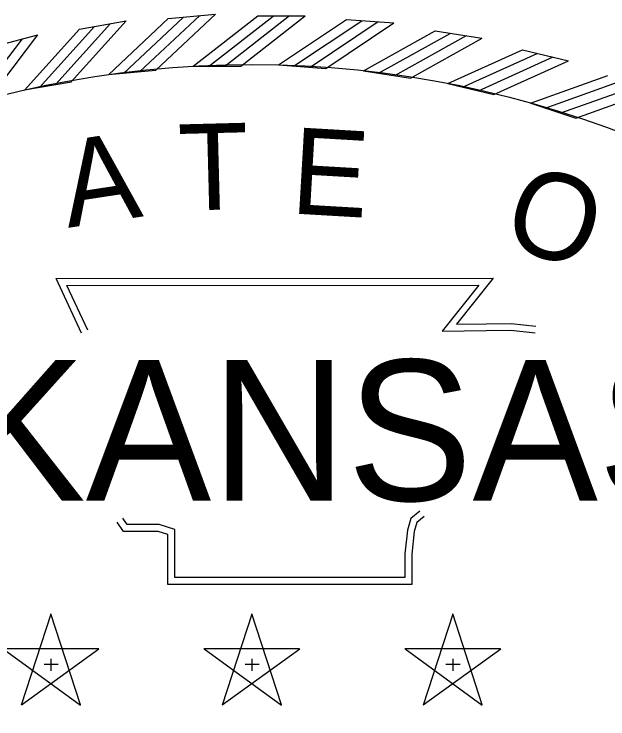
# Model space of a CAD drawing. Extents: x 18 to 1228740, y 11 to 152440.
# Drawn here: x 17.7475 to 17.7948, y 10.9361 to 10.9922 of the extents above; entities that cross this region are included whole.
import ezdxf

# ---------------------------------------------------------------- set-up
doc = ezdxf.new("R2010")
doc.units = 0
for name, color, linetype in [('B_StampERBB', 7, 'Continuous'), ('B_StampHSS', 7, 'Continuous'), ('B_StampJSB', 7, 'Continuous'), ('B_StampSCR', 7, 'Continuous'), ('B_StampSFH', 7, 'Continuous')]:
    doc.layers.add(name, color=color, linetype=linetype)

msp = doc.modelspace()

# ---------------------------------------------------------------- linework, layer by layer
at = {"layer": 'B_StampERBB'}
for p, q in [((17.759782, 10.99184), (17.763536, 10.992186)), ((17.766921, 10.99205), (17.770691, 10.99205)), ((17.752726, 10.990997), (17.756438, 10.991651)), ((17.773983, 10.991767), (17.777742, 10.991491)), ((17.745763, 10.989574), (17.749409, 10.990533)), ((17.78103, 10.990852), (17.784754, 10.990266)), ((17.787978, 10.989358), (17.791641, 10.988467)), ((17.768557, 10.988144), (17.772326, 10.987867)), ((17.755027, 10.987373), (17.75879, 10.98772)), ((17.761776, 10.988038), (17.765555, 10.988038)), ((17.775324, 10.987689), (17.779057, 10.987102)), ((17.748356, 10.986153), (17.752077, 10.986809)), ((17.78203, 10.986678), (17.785702, 10.985784)), ((17.78863, 10.985115), (17.792215, 10.983921)), ((17.750447, 10.944483), (17.748088, 10.937247)), ((17.752797, 10.937251), (17.750452, 10.944492)), ((17.766438, 10.944483), (17.764079, 10.937247)), ((17.768788, 10.937251), (17.766443, 10.944492)), ((17.782429, 10.944483), (17.78007, 10.937247)), ((17.784779, 10.937251), (17.782434, 10.944492)), ((17.754249, 10.941721), (17.746638, 10.941728)), ((17.746645, 10.941721), (17.752798, 10.937242)), ((17.748097, 10.937251), (17.754258, 10.941719)), ((17.77024, 10.941721), (17.762629, 10.941728)), ((17.762636, 10.941721), (17.768789, 10.937242)), ((17.764088, 10.937251), (17.770249, 10.941719)), ((17.786231, 10.941721), (17.77862, 10.941728)), ((17.778627, 10.941721), (17.78478, 10.937242)), ((17.780079, 10.937251), (17.786241, 10.941719)), ((17.749905, 10.940505), (17.751036, 10.940505)), ((17.750454, 10.940912), (17.750454, 10.939957)), ((17.765896, 10.940505), (17.767027, 10.940505)), ((17.766445, 10.940912), (17.766445, 10.939957)), ((17.781887, 10.940505), (17.783018, 10.940505)), ((17.782436, 10.940912), (17.782436, 10.939957))]:
    msp.add_line(p, q, dxfattribs=at)
for points in [[(17.757534, 10.987618), (17.762288, 10.992085)], [(17.758785, 10.987722), (17.763539, 10.992189)], [(17.761772, 10.988035), (17.766915, 10.992046)], [(17.764295, 10.988053), (17.769438, 10.992064)], [(17.765551, 10.988041), (17.770694, 10.992053)], [(17.752072, 10.986811), (17.756441, 10.991655)], [(17.755023, 10.987369), (17.759777, 10.991836)], [(17.756232, 10.987469), (17.760986, 10.991936)], [(17.762985, 10.988024), (17.768129, 10.992035)], [(17.768553, 10.988141), (17.773977, 10.991764)], [(17.769762, 10.988041), (17.775186, 10.991664)], [(17.77107, 10.987973), (17.776494, 10.991597)], [(17.772322, 10.98787), (17.777746, 10.991493)], [(17.748352, 10.986148), (17.752721, 10.990992)], [(17.749549, 10.986348), (17.753918, 10.991192)], [(17.750833, 10.986604), (17.755202, 10.991448)], [(17.745458, 10.985348), (17.749412, 10.990536)], [(17.775319, 10.987687), (17.781024, 10.99085)], [(17.776516, 10.987487), (17.782221, 10.99065)], [(17.777814, 10.987312), (17.783519, 10.990475)], [(17.74424, 10.98504), (17.748194, 10.990228)], [(17.779053, 10.987105), (17.784758, 10.990268)], [(17.782025, 10.986675), (17.787972, 10.989356)], [(17.783201, 10.986377), (17.789148, 10.989058)], [(17.78448, 10.986096), (17.790427, 10.988777)], [(17.785698, 10.985787), (17.791645, 10.988468)], [(17.788624, 10.985113), (17.794772, 10.987294)], [(17.789772, 10.984719), (17.79592, 10.9869)], [(17.791024, 10.984333), (17.797171, 10.986514)], [(17.792211, 10.983925), (17.798359, 10.986106)], [(17.752875, 10.966818), (17.750865, 10.97117), (17.785635, 10.97119), (17.78273, 10.96754), (17.785092, 10.967571), (17.787065, 10.967597), (17.789037, 10.967382)], [(17.753375, 10.967049), (17.751726, 10.97062), (17.784493, 10.970639), (17.781576, 10.966974), (17.785099, 10.96702), (17.787039, 10.967045), (17.788977, 10.966834)], [(17.780156, 10.952247), (17.779563, 10.951765), (17.779366, 10.951044), (17.77917, 10.949241), (17.77917, 10.946838), (17.75976, 10.946838), (17.75976, 10.950082), (17.75976, 10.950803), (17.758973, 10.951044), (17.756212, 10.951044), (17.755721, 10.951792)], [(17.779808, 10.952675), (17.779078, 10.95208), (17.778824, 10.951147), (17.778619, 10.949271), (17.778619, 10.947388), (17.760311, 10.947388), (17.760311, 10.950082), (17.760311, 10.951211), (17.759055, 10.951594), (17.756509, 10.951594), (17.756182, 10.952094)]]:
    msp.add_lwpolyline(points, dxfattribs=at)
at = {"layer": 'B_StampHSS'}
for p, q in [((17.759782, 10.99184), (17.763536, 10.992186)), ((17.766921, 10.99205), (17.770691, 10.99205)), ((17.752726, 10.990997), (17.756438, 10.991651)), ((17.773983, 10.991767), (17.777742, 10.991491)), ((17.745763, 10.989574), (17.749409, 10.990533)), ((17.78103, 10.990852), (17.784754, 10.990266)), ((17.787978, 10.989358), (17.791641, 10.988467)), ((17.768557, 10.988144), (17.772326, 10.987867)), ((17.755027, 10.987373), (17.75879, 10.98772)), ((17.761776, 10.988038), (17.765555, 10.988038)), ((17.775324, 10.987689), (17.779057, 10.987102)), ((17.748356, 10.986153), (17.752077, 10.986809)), ((17.78203, 10.986678), (17.785702, 10.985784)), ((17.78863, 10.985115), (17.792215, 10.983921)), ((17.750447, 10.944483), (17.748088, 10.937247)), ((17.752797, 10.937251), (17.750452, 10.944492)), ((17.766438, 10.944483), (17.764079, 10.937247)), ((17.768788, 10.937251), (17.766443, 10.944492)), ((17.782429, 10.944483), (17.78007, 10.937247)), ((17.784779, 10.937251), (17.782434, 10.944492)), ((17.754249, 10.941721), (17.746638, 10.941728)), ((17.746645, 10.941721), (17.752798, 10.937242)), ((17.748097, 10.937251), (17.754258, 10.941719)), ((17.77024, 10.941721), (17.762629, 10.941728)), ((17.762636, 10.941721), (17.768789, 10.937242)), ((17.764088, 10.937251), (17.770249, 10.941719)), ((17.786231, 10.941721), (17.77862, 10.941728)), ((17.778627, 10.941721), (17.78478, 10.937242)), ((17.780079, 10.937251), (17.786241, 10.941719)), ((17.749905, 10.940505), (17.751036, 10.940505)), ((17.750454, 10.940912), (17.750454, 10.939957)), ((17.765896, 10.940505), (17.767027, 10.940505)), ((17.766445, 10.940912), (17.766445, 10.939957)), ((17.781887, 10.940505), (17.783018, 10.940505)), ((17.782436, 10.940912), (17.782436, 10.939957))]:
    msp.add_line(p, q, dxfattribs=at)
for points in [[(17.757534, 10.987618), (17.762288, 10.992085)], [(17.758785, 10.987722), (17.763539, 10.992189)], [(17.761772, 10.988035), (17.766915, 10.992046)], [(17.764295, 10.988053), (17.769438, 10.992064)], [(17.765551, 10.988041), (17.770694, 10.992053)], [(17.752072, 10.986811), (17.756441, 10.991655)], [(17.755023, 10.987369), (17.759777, 10.991836)], [(17.756232, 10.987469), (17.760986, 10.991936)], [(17.762985, 10.988024), (17.768129, 10.992035)], [(17.768553, 10.988141), (17.773977, 10.991764)], [(17.769762, 10.988041), (17.775186, 10.991664)], [(17.77107, 10.987973), (17.776494, 10.991597)], [(17.772322, 10.98787), (17.777746, 10.991493)], [(17.748352, 10.986148), (17.752721, 10.990992)], [(17.749549, 10.986348), (17.753918, 10.991192)], [(17.750833, 10.986604), (17.755202, 10.991448)], [(17.745458, 10.985348), (17.749412, 10.990536)], [(17.775319, 10.987687), (17.781024, 10.99085)], [(17.776516, 10.987487), (17.782221, 10.99065)], [(17.777814, 10.987312), (17.783519, 10.990475)], [(17.74424, 10.98504), (17.748194, 10.990228)], [(17.779053, 10.987105), (17.784758, 10.990268)], [(17.782025, 10.986675), (17.787972, 10.989356)], [(17.783201, 10.986377), (17.789148, 10.989058)], [(17.78448, 10.986096), (17.790427, 10.988777)], [(17.785698, 10.985787), (17.791645, 10.988468)], [(17.788624, 10.985113), (17.794772, 10.987294)], [(17.789772, 10.984719), (17.79592, 10.9869)], [(17.791024, 10.984333), (17.797171, 10.986514)], [(17.792211, 10.983925), (17.798359, 10.986106)], [(17.752875, 10.966818), (17.750865, 10.97117), (17.785635, 10.97119), (17.78273, 10.96754), (17.785092, 10.967571), (17.787065, 10.967597), (17.789037, 10.967382)], [(17.753375, 10.967049), (17.751726, 10.97062), (17.784493, 10.970639), (17.781576, 10.966974), (17.785099, 10.96702), (17.787039, 10.967045), (17.788977, 10.966834)], [(17.780156, 10.952247), (17.779563, 10.951765), (17.779366, 10.951044), (17.77917, 10.949241), (17.77917, 10.946838), (17.75976, 10.946838), (17.75976, 10.950082), (17.75976, 10.950803), (17.758973, 10.951044), (17.756212, 10.951044), (17.755721, 10.951792)], [(17.779808, 10.952675), (17.779078, 10.95208), (17.778824, 10.951147), (17.778619, 10.949271), (17.778619, 10.947388), (17.760311, 10.947388), (17.760311, 10.950082), (17.760311, 10.951211), (17.759055, 10.951594), (17.756509, 10.951594), (17.756182, 10.952094)]]:
    msp.add_lwpolyline(points, dxfattribs=at)
at = {"layer": 'B_StampJSB'}
for p, q in [((17.759782, 10.99184), (17.763536, 10.992186)), ((17.766921, 10.99205), (17.770691, 10.99205)), ((17.752726, 10.990997), (17.756438, 10.991651)), ((17.773983, 10.991767), (17.777742, 10.991491)), ((17.745763, 10.989574), (17.749409, 10.990533)), ((17.78103, 10.990852), (17.784754, 10.990266)), ((17.787978, 10.989358), (17.791641, 10.988467)), ((17.768557, 10.988144), (17.772326, 10.987867)), ((17.755027, 10.987373), (17.75879, 10.98772)), ((17.761776, 10.988038), (17.765555, 10.988038)), ((17.775324, 10.987689), (17.779057, 10.987102)), ((17.748356, 10.986153), (17.752077, 10.986809)), ((17.78203, 10.986678), (17.785702, 10.985784)), ((17.78863, 10.985115), (17.792215, 10.983921)), ((17.750447, 10.944483), (17.748088, 10.937247)), ((17.752797, 10.937251), (17.750452, 10.944492)), ((17.766438, 10.944483), (17.764079, 10.937247)), ((17.768788, 10.937251), (17.766443, 10.944492)), ((17.782429, 10.944483), (17.78007, 10.937247)), ((17.784779, 10.937251), (17.782434, 10.944492)), ((17.754249, 10.941721), (17.746638, 10.941728)), ((17.746645, 10.941721), (17.752798, 10.937242)), ((17.748097, 10.937251), (17.754258, 10.941719)), ((17.77024, 10.941721), (17.762629, 10.941728)), ((17.762636, 10.941721), (17.768789, 10.937242)), ((17.764088, 10.937251), (17.770249, 10.941719)), ((17.786231, 10.941721), (17.77862, 10.941728)), ((17.778627, 10.941721), (17.78478, 10.937242)), ((17.780079, 10.937251), (17.786241, 10.941719)), ((17.749905, 10.940505), (17.751036, 10.940505)), ((17.750454, 10.940912), (17.750454, 10.939957)), ((17.765896, 10.940505), (17.767027, 10.940505)), ((17.766445, 10.940912), (17.766445, 10.939957)), ((17.781887, 10.940505), (17.783018, 10.940505)), ((17.782436, 10.940912), (17.782436, 10.939957))]:
    msp.add_line(p, q, dxfattribs=at)
for points in [[(17.757534, 10.987618), (17.762288, 10.992085)], [(17.758785, 10.987722), (17.763539, 10.992189)], [(17.761772, 10.988035), (17.766915, 10.992046)], [(17.764295, 10.988053), (17.769438, 10.992064)], [(17.765551, 10.988041), (17.770694, 10.992053)], [(17.752072, 10.986811), (17.756441, 10.991655)], [(17.755023, 10.987369), (17.759777, 10.991836)], [(17.756232, 10.987469), (17.760986, 10.991936)], [(17.762985, 10.988024), (17.768129, 10.992035)], [(17.768553, 10.988141), (17.773977, 10.991764)], [(17.769762, 10.988041), (17.775186, 10.991664)], [(17.77107, 10.987973), (17.776494, 10.991597)], [(17.772322, 10.98787), (17.777746, 10.991493)], [(17.748352, 10.986148), (17.752721, 10.990992)], [(17.749549, 10.986348), (17.753918, 10.991192)], [(17.750833, 10.986604), (17.755202, 10.991448)], [(17.745458, 10.985348), (17.749412, 10.990536)], [(17.775319, 10.987687), (17.781024, 10.99085)], [(17.776516, 10.987487), (17.782221, 10.99065)], [(17.777814, 10.987312), (17.783519, 10.990475)], [(17.74424, 10.98504), (17.748194, 10.990228)], [(17.779053, 10.987105), (17.784758, 10.990268)], [(17.782025, 10.986675), (17.787972, 10.989356)], [(17.783201, 10.986377), (17.789148, 10.989058)], [(17.78448, 10.986096), (17.790427, 10.988777)], [(17.785698, 10.985787), (17.791645, 10.988468)], [(17.788624, 10.985113), (17.794772, 10.987294)], [(17.789772, 10.984719), (17.79592, 10.9869)], [(17.791024, 10.984333), (17.797171, 10.986514)], [(17.792211, 10.983925), (17.798359, 10.986106)], [(17.752875, 10.966818), (17.750865, 10.97117), (17.785635, 10.97119), (17.78273, 10.96754), (17.785092, 10.967571), (17.787065, 10.967597), (17.789037, 10.967382)], [(17.753375, 10.967049), (17.751726, 10.97062), (17.784493, 10.970639), (17.781576, 10.966974), (17.785099, 10.96702), (17.787039, 10.967045), (17.788977, 10.966834)], [(17.780156, 10.952247), (17.779563, 10.951765), (17.779366, 10.951044), (17.77917, 10.949241), (17.77917, 10.946838), (17.75976, 10.946838), (17.75976, 10.950082), (17.75976, 10.950803), (17.758973, 10.951044), (17.756212, 10.951044), (17.755721, 10.951792)], [(17.779808, 10.952675), (17.779078, 10.95208), (17.778824, 10.951147), (17.778619, 10.949271), (17.778619, 10.947388), (17.760311, 10.947388), (17.760311, 10.950082), (17.760311, 10.951211), (17.759055, 10.951594), (17.756509, 10.951594), (17.756182, 10.952094)]]:
    msp.add_lwpolyline(points, dxfattribs=at)
msp.add_circle((17.766447, 10.906117), 0.082054, dxfattribs=at)
at = {"layer": 'B_StampSCR'}
for p, q in [((17.759782, 10.99184), (17.763536, 10.992186)), ((17.766921, 10.99205), (17.770691, 10.99205)), ((17.752726, 10.990997), (17.756438, 10.991651)), ((17.773983, 10.991767), (17.777742, 10.991491)), ((17.745763, 10.989574), (17.749409, 10.990533)), ((17.78103, 10.990852), (17.784754, 10.990266)), ((17.787978, 10.989358), (17.791641, 10.988467)), ((17.768557, 10.988144), (17.772326, 10.987867)), ((17.755027, 10.987373), (17.75879, 10.98772)), ((17.761776, 10.988038), (17.765555, 10.988038)), ((17.775324, 10.987689), (17.779057, 10.987102)), ((17.748356, 10.986153), (17.752077, 10.986809)), ((17.78203, 10.986678), (17.785702, 10.985784)), ((17.78863, 10.985115), (17.792215, 10.983921)), ((17.750447, 10.944483), (17.748088, 10.937247)), ((17.752797, 10.937251), (17.750452, 10.944492)), ((17.766438, 10.944483), (17.764079, 10.937247)), ((17.768788, 10.937251), (17.766443, 10.944492)), ((17.782429, 10.944483), (17.78007, 10.937247)), ((17.784779, 10.937251), (17.782434, 10.944492)), ((17.754249, 10.941721), (17.746638, 10.941728)), ((17.746645, 10.941721), (17.752798, 10.937242)), ((17.748097, 10.937251), (17.754258, 10.941719)), ((17.77024, 10.941721), (17.762629, 10.941728)), ((17.762636, 10.941721), (17.768789, 10.937242)), ((17.764088, 10.937251), (17.770249, 10.941719)), ((17.786231, 10.941721), (17.77862, 10.941728)), ((17.778627, 10.941721), (17.78478, 10.937242)), ((17.780079, 10.937251), (17.786241, 10.941719)), ((17.749905, 10.940505), (17.751036, 10.940505)), ((17.750454, 10.940912), (17.750454, 10.939957)), ((17.765896, 10.940505), (17.767027, 10.940505)), ((17.766445, 10.940912), (17.766445, 10.939957)), ((17.781887, 10.940505), (17.783018, 10.940505)), ((17.782436, 10.940912), (17.782436, 10.939957))]:
    msp.add_line(p, q, dxfattribs=at)
for points in [[(17.757534, 10.987618), (17.762288, 10.992085)], [(17.758785, 10.987722), (17.763539, 10.992189)], [(17.761772, 10.988035), (17.766915, 10.992046)], [(17.764295, 10.988053), (17.769438, 10.992064)], [(17.765551, 10.988041), (17.770694, 10.992053)], [(17.752072, 10.986811), (17.756441, 10.991655)], [(17.755023, 10.987369), (17.759777, 10.991836)], [(17.756232, 10.987469), (17.760986, 10.991936)], [(17.762985, 10.988024), (17.768129, 10.992035)], [(17.768553, 10.988141), (17.773977, 10.991764)], [(17.769762, 10.988041), (17.775186, 10.991664)], [(17.77107, 10.987973), (17.776494, 10.991597)], [(17.772322, 10.98787), (17.777746, 10.991493)], [(17.748352, 10.986148), (17.752721, 10.990992)], [(17.749549, 10.986348), (17.753918, 10.991192)], [(17.750833, 10.986604), (17.755202, 10.991448)], [(17.745458, 10.985348), (17.749412, 10.990536)], [(17.775319, 10.987687), (17.781024, 10.99085)], [(17.776516, 10.987487), (17.782221, 10.99065)], [(17.777814, 10.987312), (17.783519, 10.990475)], [(17.74424, 10.98504), (17.748194, 10.990228)], [(17.779053, 10.987105), (17.784758, 10.990268)], [(17.782025, 10.986675), (17.787972, 10.989356)], [(17.783201, 10.986377), (17.789148, 10.989058)], [(17.78448, 10.986096), (17.790427, 10.988777)], [(17.785698, 10.985787), (17.791645, 10.988468)], [(17.788624, 10.985113), (17.794772, 10.987294)], [(17.789772, 10.984719), (17.79592, 10.9869)], [(17.791024, 10.984333), (17.797171, 10.986514)], [(17.792211, 10.983925), (17.798359, 10.986106)], [(17.752875, 10.966818), (17.750865, 10.97117), (17.785635, 10.97119), (17.78273, 10.96754), (17.785092, 10.967571), (17.787065, 10.967597), (17.789037, 10.967382)], [(17.753375, 10.967049), (17.751726, 10.97062), (17.784493, 10.970639), (17.781576, 10.966974), (17.785099, 10.96702), (17.787039, 10.967045), (17.788977, 10.966834)], [(17.780156, 10.952247), (17.779563, 10.951765), (17.779366, 10.951044), (17.77917, 10.949241), (17.77917, 10.946838), (17.75976, 10.946838), (17.75976, 10.950082), (17.75976, 10.950803), (17.758973, 10.951044), (17.756212, 10.951044), (17.755721, 10.951792)], [(17.779808, 10.952675), (17.779078, 10.95208), (17.778824, 10.951147), (17.778619, 10.949271), (17.778619, 10.947388), (17.760311, 10.947388), (17.760311, 10.950082), (17.760311, 10.951211), (17.759055, 10.951594), (17.756509, 10.951594), (17.756182, 10.952094)]]:
    msp.add_lwpolyline(points, dxfattribs=at)
at = {"layer": 'B_StampSFH'}
for p, q in [((17.759782, 10.99184), (17.763536, 10.992186)), ((17.766921, 10.99205), (17.770691, 10.99205)), ((17.752726, 10.990997), (17.756438, 10.991651)), ((17.773983, 10.991767), (17.777742, 10.991491)), ((17.745763, 10.989574), (17.749409, 10.990533)), ((17.78103, 10.990852), (17.784754, 10.990266)), ((17.787978, 10.989358), (17.791641, 10.988467)), ((17.768557, 10.988144), (17.772326, 10.987867)), ((17.755027, 10.987373), (17.75879, 10.98772)), ((17.761776, 10.988038), (17.765555, 10.988038)), ((17.775324, 10.987689), (17.779057, 10.987102)), ((17.748356, 10.986153), (17.752077, 10.986809)), ((17.78203, 10.986678), (17.785702, 10.985784)), ((17.78863, 10.985115), (17.792215, 10.983921)), ((17.750447, 10.944483), (17.748088, 10.937247)), ((17.752797, 10.937251), (17.750452, 10.944492)), ((17.766438, 10.944483), (17.764079, 10.937247)), ((17.768788, 10.937251), (17.766443, 10.944492)), ((17.782429, 10.944483), (17.78007, 10.937247)), ((17.784779, 10.937251), (17.782434, 10.944492)), ((17.754249, 10.941721), (17.746638, 10.941728)), ((17.746645, 10.941721), (17.752798, 10.937242)), ((17.748097, 10.937251), (17.754258, 10.941719)), ((17.77024, 10.941721), (17.762629, 10.941728)), ((17.762636, 10.941721), (17.768789, 10.937242)), ((17.764088, 10.937251), (17.770249, 10.941719)), ((17.786231, 10.941721), (17.77862, 10.941728)), ((17.778627, 10.941721), (17.78478, 10.937242)), ((17.780079, 10.937251), (17.786241, 10.941719)), ((17.749905, 10.940505), (17.751036, 10.940505)), ((17.750454, 10.940912), (17.750454, 10.939957)), ((17.765896, 10.940505), (17.767027, 10.940505)), ((17.766445, 10.940912), (17.766445, 10.939957)), ((17.781887, 10.940505), (17.783018, 10.940505)), ((17.782436, 10.940912), (17.782436, 10.939957))]:
    msp.add_line(p, q, dxfattribs=at)
for points in [[(17.757534, 10.987618), (17.762288, 10.992085)], [(17.758785, 10.987722), (17.763539, 10.992189)], [(17.761772, 10.988035), (17.766915, 10.992046)], [(17.764295, 10.988053), (17.769438, 10.992064)], [(17.765551, 10.988041), (17.770694, 10.992053)], [(17.752072, 10.986811), (17.756441, 10.991655)], [(17.755023, 10.987369), (17.759777, 10.991836)], [(17.756232, 10.987469), (17.760986, 10.991936)], [(17.762985, 10.988024), (17.768129, 10.992035)], [(17.768553, 10.988141), (17.773977, 10.991764)], [(17.769762, 10.988041), (17.775186, 10.991664)], [(17.77107, 10.987973), (17.776494, 10.991597)], [(17.772322, 10.98787), (17.777746, 10.991493)], [(17.748352, 10.986148), (17.752721, 10.990992)], [(17.749549, 10.986348), (17.753918, 10.991192)], [(17.750833, 10.986604), (17.755202, 10.991448)], [(17.745458, 10.985348), (17.749412, 10.990536)], [(17.775319, 10.987687), (17.781024, 10.99085)], [(17.776516, 10.987487), (17.782221, 10.99065)], [(17.777814, 10.987312), (17.783519, 10.990475)], [(17.74424, 10.98504), (17.748194, 10.990228)], [(17.779053, 10.987105), (17.784758, 10.990268)], [(17.782025, 10.986675), (17.787972, 10.989356)], [(17.783201, 10.986377), (17.789148, 10.989058)], [(17.78448, 10.986096), (17.790427, 10.988777)], [(17.785698, 10.985787), (17.791645, 10.988468)], [(17.788624, 10.985113), (17.794772, 10.987294)], [(17.789772, 10.984719), (17.79592, 10.9869)], [(17.791024, 10.984333), (17.797171, 10.986514)], [(17.792211, 10.983925), (17.798359, 10.986106)], [(17.752875, 10.966818), (17.750865, 10.97117), (17.785635, 10.97119), (17.78273, 10.96754), (17.785092, 10.967571), (17.787065, 10.967597), (17.789037, 10.967382)], [(17.753375, 10.967049), (17.751726, 10.97062), (17.784493, 10.970639), (17.781576, 10.966974), (17.785099, 10.96702), (17.787039, 10.967045), (17.788977, 10.966834)], [(17.780156, 10.952247), (17.779563, 10.951765), (17.779366, 10.951044), (17.77917, 10.949241), (17.77917, 10.946838), (17.75976, 10.946838), (17.75976, 10.950082), (17.75976, 10.950803), (17.758973, 10.951044), (17.756212, 10.951044), (17.755721, 10.951792)], [(17.779808, 10.952675), (17.779078, 10.95208), (17.778824, 10.951147), (17.778619, 10.949271), (17.778619, 10.947388), (17.760311, 10.947388), (17.760311, 10.950082), (17.760311, 10.951211), (17.759055, 10.951594), (17.756509, 10.951594), (17.756182, 10.952094)]]:
    msp.add_lwpolyline(points, dxfattribs=at)

# ---------------------------------------------------------------- texts
at = {"layer": 'B_StampERBB'}
for s, rotation, p in [('T', 1.4789, (17.760672, 10.976553)), ('E', 356.672, (17.769449, 10.976345)), ('A', 8.6788, (17.751815, 10.975189)), ('O', 341.2218, (17.786102, 10.973993))]:
    msp.add_text(s, height=0.006859, rotation=rotation, dxfattribs=at).set_placement(p)
msp.add_text('ARKANSAS', height=0.0111938, dxfattribs=at).set_placement((17.722443, 10.953498))
at = {"layer": 'B_StampHSS'}
for s, rotation, p in [('T', 1.4789, (17.760672, 10.976553)), ('E', 356.672, (17.769449, 10.976345)), ('A', 8.6788, (17.751815, 10.975189)), ('O', 341.2218, (17.786102, 10.973993))]:
    msp.add_text(s, height=0.006859, rotation=rotation, dxfattribs=at).set_placement(p)
msp.add_text('ARKANSAS', height=0.0111938, dxfattribs=at).set_placement((17.722443, 10.953498))
at = {"layer": 'B_StampJSB'}
for s, rotation, p in [('T', 1.4789, (17.760672, 10.976553)), ('E', 356.672, (17.769449, 10.976345)), ('A', 8.6788, (17.751815, 10.975189)), ('O', 341.2218, (17.786102, 10.973993))]:
    msp.add_text(s, height=0.006859, rotation=rotation, dxfattribs=at).set_placement(p)
msp.add_text('ARKANSAS', height=0.0111938, dxfattribs=at).set_placement((17.722443, 10.953498))
at = {"layer": 'B_StampSCR'}
for s, rotation, p in [('T', 1.4789, (17.760672, 10.976553)), ('E', 356.672, (17.769449, 10.976345)), ('A', 8.6788, (17.751815, 10.975189)), ('O', 341.2218, (17.786102, 10.973993))]:
    msp.add_text(s, height=0.006859, rotation=rotation, dxfattribs=at).set_placement(p)
msp.add_text('ARKANSAS', height=0.0111938, dxfattribs=at).set_placement((17.722443, 10.953498))
at = {"layer": 'B_StampSFH'}
for s, rotation, p in [('T', 1.4789, (17.760672, 10.976553)), ('E', 356.672, (17.769449, 10.976345)), ('A', 8.6788, (17.751815, 10.975189)), ('O', 341.2218, (17.786102, 10.973993))]:
    msp.add_text(s, height=0.006859, rotation=rotation, dxfattribs=at).set_placement(p)
msp.add_text('ARKANSAS', height=0.0111938, dxfattribs=at).set_placement((17.722443, 10.953498))

doc.saveas('drawing.dxf')
